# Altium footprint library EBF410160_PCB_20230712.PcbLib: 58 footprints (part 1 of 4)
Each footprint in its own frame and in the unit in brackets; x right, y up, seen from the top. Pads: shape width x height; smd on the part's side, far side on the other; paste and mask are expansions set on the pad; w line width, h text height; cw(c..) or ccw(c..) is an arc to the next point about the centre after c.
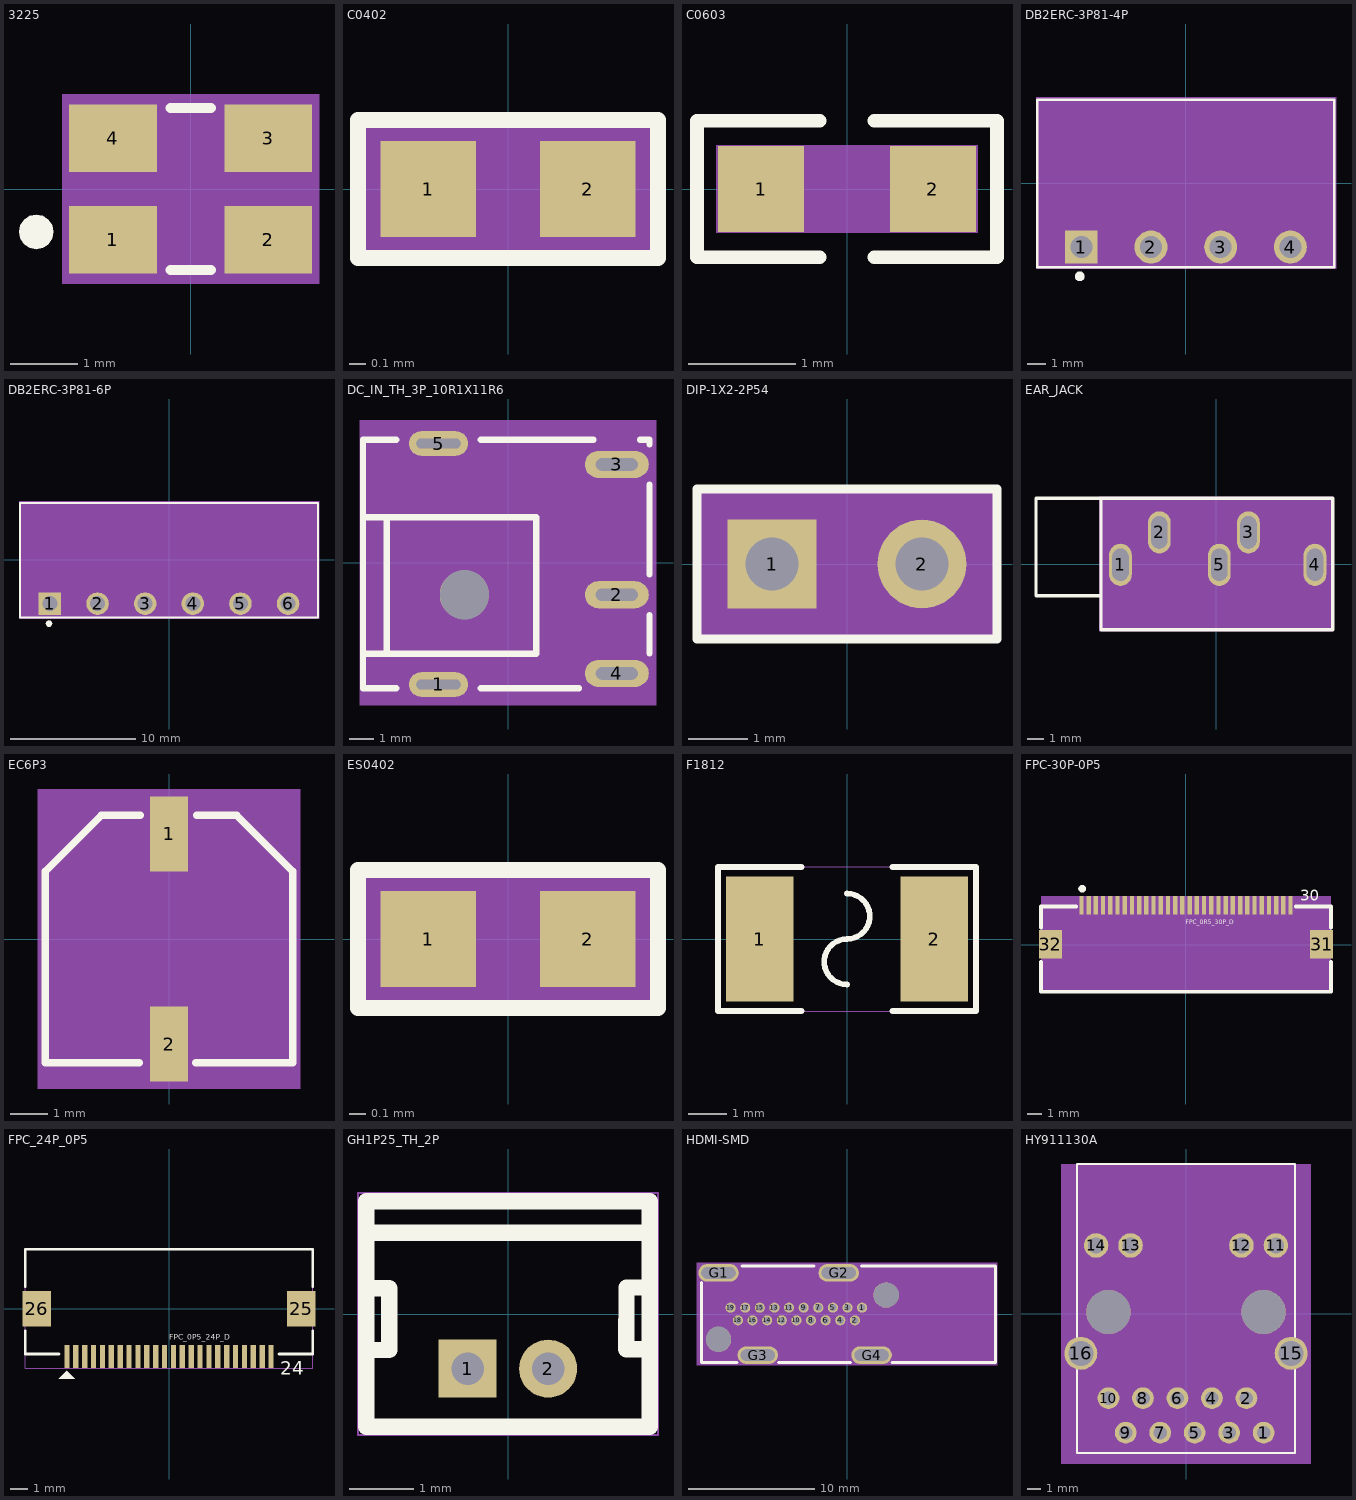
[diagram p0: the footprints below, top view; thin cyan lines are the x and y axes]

## 3225 [mm] "3225"
pads (4):
  rect 1.3x1 smd: 1(-1.15,-0.75) 2(1.15,-0.75) 3(1.15,0.75) 4(-1.15,0.75)
Top Overlay:
  dashed: -2.541,-0.635 -2.521,-0.733 -2.466,-0.815 -2.384,-0.87 -2.286,-0.89 -2.188,-0.87 -2.161,-0.852 -2.106,-0.815 -2.051,-0.733 -2.031,-0.635 -2.051,-0.537 -2.106,-0.455 -2.161,-0.418 -2.188,-0.4 -2.286,-0.38 -2.384,-0.4 -2.466,-0.455 -2.521,-0.537
  lines w0.15: -0.3,-1.2 0.3,-1.2 ; -0.3,1.2 0.3,1.2
Top 3D Body:
  region: -1.9,1.4 -1.9,-1.4 1.9,-1.4 1.9,1.4
Mechanical 20:
  text "3" at 1.516,0.75 h0.91
  text "1" at -0.784,-0.75 h0.91
  text "4" at -0.784,0.75 h0.91
  text "2" at 1.516,-0.75 h0.91
Top Assembly:
  lines w0.15: -1.6,-1.25 -1.6,1.25 1.6,1.25 1.6,-1.25 -1.6,-1.25
3D body: height 3.81, standoff 0, extent -1.9,-1.4 1.9,1.4

## C0402 [mm] "C0402"
pads (2):
  rect 0.599x0.599 smd: 1(-0.5,0) 2(0.5,0)
Top Overlay:
  lines w0.102: -0.94,-0.432 0.94,-0.432 0.94,0.432 -0.94,0.432 -0.94,-0.432
Top 3D Body:
  region: 0.94,0.432 0.94,-0.432 -0.94,-0.432 -0.94,0.432
Mechanical 20:
  text "1" at -0.5,0.254 h0.64
  text "2" at 0.5,0.254 h0.64
Top Assembly:
  dashed: -0.94,-0.432 -0.94,0.432 0.94,0.432 0.94,-0.432
3D body: height 3.81, standoff 0, extent -0.94,-0.432 0.94,0.432

## C0603 [mil] "C0603"
pads (2):
  rect 31.5x31.5 smd: 1(-31.5,0) 2(31.5,0)
Top Overlay:
  lines w5: -10,-25 -55,-25 -55,25 -10,25 ; 10,-25 55,-25 55,25 10,25
Top 3D Body:
  region: -48,16 48,16 48,-16 -48,-16
Mechanical 20:
  text "1" at -13.5,0 h45
  text "2" at 49.5,0 h45
Top Assembly:
  text "C0603" at -117,37 h45
3D body: height 150, standoff 0, extent -48,-16 48,16

## DB2ERC-3P81-4P [mm] "DB2ERC-3P81-4P"
pads (4):
  rect 1.8x1.8 / inner round 1.524 / far side rect 1.8x1.8 hole 1.2: 1(-5.725,-3.5)
  round 1.8 / inner round 1.524 / far side round 1.8 hole 1.2: 2(-1.915,-3.5) 3(1.895,-3.5) 4(5.705,-3.5)
Top Overlay:
  dashed: -6.065,-5.1 -6.045,-5.198 -5.99,-5.28 -5.908,-5.335 -5.81,-5.355 -5.712,-5.335 -5.685,-5.317 -5.63,-5.28 -5.574,-5.198 -5.555,-5.1 -5.574,-5.002 -5.63,-4.92 -5.685,-4.883 -5.712,-4.864 -5.81,-4.845 -5.908,-4.864 -5.99,-4.92 -6.045,-5.002
  lines w0.15: -8.13,-4.6 -8.13,4.55 8.11,4.55 8.11,-4.6 -8.13,-4.6
Top 3D Body:
  region: -8.2,4.7 -8.2,-4.7 8.2,-4.7 8.2,4.7
Mechanical 20:
  text "4" at 5.959,-3.5 h0.64
  text "3" at 2.149,-3.5 h0.64
  text "2" at -1.661,-3.5 h0.64
  text "1" at -5.471,-3.5 h0.64
3D body: height 3.81, standoff 0, extent -8.2,-4.7 8.2,4.7

## DB2ERC-3P81-6P [mm] "DB2ERC-3P81-6P"
pads (6):
  rect 1.8x1.8 / inner round 1.524 / far side rect 1.8x1.8 hole 1.2: 1(-9.525,-3.5)
  round 1.8 hole 1.2: 2(-5.715,-3.5) 5(5.715,-3.5)
  round 1.8 / inner round 1.524 / far side round 1.8 hole 1.2: 3(-1.905,-3.5) 4(1.905,-3.5) 6(9.525,-3.5)
Top Overlay:
  dashed: -9.855,-5.1 -9.836,-5.198 -9.78,-5.28 -9.698,-5.335 -9.6,-5.355 -9.502,-5.335 -9.475,-5.317 -9.42,-5.28 -9.364,-5.198 -9.345,-5.1 -9.364,-5.002 -9.42,-4.92 -9.475,-4.883 -9.502,-4.864 -9.6,-4.845 -9.698,-4.864 -9.78,-4.92 -9.836,-5.002
  lines w0.15: -11.93,-4.6 -11.93,4.55 11.93,4.55 11.93,-4.6 -11.93,-4.6
Top 3D Body:
  region: -12,4.7 -12,-4.7 12,-4.7 12,4.7
Mechanical 20:
  text "6" at 9.779,-3.5 h0.64
  text "4" at 2.159,-3.5 h0.64
  text "2" at -5.461,-3.5 h0.64
  text "5" at 5.969,-3.5 h0.64
  text "1" at -9.271,-3.5 h0.64
  text "3" at -1.651,-3.5 h0.64
3D body: height 3.81, standoff 0, extent -12,-4.7 12,4.7

## DC_IN_TH_3P_10R1X11R6 [mil] "DC_IN_TH_3P_10R1X11R6"
pads (6):
  oval 94.5x39.4 hole 70.9 slot 15.7 at 90 deg: 1(-111.25,-194.9) 5(-111.25,190.9)
  oval 102.4x43.3 hole 66.9 slot 19.7 at 90 deg: 2(174.25,-51.2) 3(174.25,157.4)
  oval 102.4x43.3 / inner round 60 / far side oval 102.4x43.3 hole 66.9 slot 19.7 at 90 deg: 4(174.25,-177.2)
  round 78.7 hole 78.7 unplated: ""(-69.85,-51.2)
Top Overlay:
  lines w10: -232.25,-145.7 45.25,-145.7 45.25,72.8 -222.45,72.8 -232.25,72.8 ; -193.95,-145.7 -193.95,72.8 ; -178.95,-200.8 -232.25,-200.8 -232.25,196.8 -178.95,196.8 ; -43.45,-200.8 113.65,-200.8 ; -43.45,196.8 136.95,196.8 ; 211.45,196.8 226.35,196.8 226.35,189.7 ; 226.35,-145 226.35,-83.5 ; 226.35,-19 226.35,125.2
Top 3D Body:
  region: -237.25,-228.4 237.25,-228.4 237.25,228.4 -237.25,228.4
Mechanical 20:
  text "4" at 174.25,-187.2 h25
  text "5" at -111.25,180.9 h25
  text "1" at -111.25,-204.9 h25
  text "2" at 174.25,-61.2 h25
  text "3" at 174.25,147.4 h25
Mechanical 23:
  dashed: -232.25,-141.8 41.35,-141.8 41.35,68.9 -232.25,68.9 -232.25,78.7 51.15,78.7 51.15,-151.6 -232.25,-151.6
3D body: height 150, standoff 0, extent -237.25,-228.4 237.25,228.4

## DIP-1X2-2P54 [mm] "DIP-1X2-2P54"
pads (2):
  rect 1.5x1.5 hole 0.9: 1(-1.27,0)
  round 1.5 / inner round 1.524 / far side round 1.5 hole 0.9: 2(1.27,0)
Top Overlay:
  lines w0.15: -2.54,-1.27 -2.54,1.27 2.54,1.27 2.54,-1.27 -2.54,-1.27
Bottom Overlay:
  lines w0.6: 0,-0.6 0,0.6
Top 3D Body:
  region: -2.54,-1.27 2.54,-1.27 2.54,1.27 -2.54,1.27
Mechanical 20:
  text "2" at 1.524,0 h0.64
  text "1" at -1.016,0 h0.64
Top Assembly:
  lines w0.025: -2.54,-1.27 -2.54,1.27 2.54,1.27 2.54,-1.27 -2.54,-1.27
3D body: height 3.81, standoff 0, extent -2.54,-1.27 2.54,1.27

## EAR_JACK [mm] "EAR_JACK"
pads (5):
  oval 1.4x2.6 / inner round 1.524 / far side oval 1.4x2.6 hole 1 slot 2 at 90 deg: 1(-5.904,-0.05) 2(-3.504,1.95) 3(1.996,1.95) 4(6.096,-0.05) 5(0.196,-0.05)
Top Overlay:
  lines w0.2: -7.18,-1.956 -11.117,-1.956 -11.117,4.064 -7.18,4.064 7.196,4.064 7.196,-4.064 -7.104,-4.064 -7.104,4.064
Top 3D Body:
  region: -7.2,-4.15 7.2,-4.15 7.2,4.15 -7.2,4.15
Mechanical 20:
  text "1" at -5.904,-0.304 h0.64
  text "5" at 0.196,-0.304 h0.64
  text "3" at 1.996,1.696 h0.64
  text "2" at -3.504,1.696 h0.64
  text "4" at 6.096,-0.304 h0.64
Top Assembly:
  dashed: -7.2,4.15 -7.2,-4.15 7.2,-4.15 7.2,4.15
3D body: height 3.81, standoff 0, extent -7.2,-4.15 7.2,4.15

## EC6P3 [mm] "EC6P3"
pads (2):
  rect 1.001x1.999 smd: 1(0,2.8) 2(0,-2.8)
Top Overlay:
  lines w0.2: -0.787,-3.3 -3.3,-3.3 -3.3,1.8 -1.8,3.3 -0.762,3.3 ; 0.711,-3.3 3.3,-3.3 3.3,1.8 1.8,3.3 0.737,3.3
Top 3D Body:
  region: -3.5,4 -3.5,-4 3.5,-4 3.5,4
Mechanical 20:
  text "1" at 0.356,2.8 h0.89
  text "2" at 0.356,-2.8 h0.89
3D body: height 3.81, standoff 0, extent -3.5,-4 3.5,4

## ES0402 [mm] "ES0402"
pads (2):
  rect 0.599x0.599 smd: 1(-0.5,0) 2(0.5,0)
Top Overlay:
  lines w0.102: -0.94,-0.432 -0.94,0.432 0.94,0.432 0.94,-0.432 -0.94,-0.432
Top 3D Body:
  region: 0.94,0.432 0.94,-0.432 -0.94,-0.432 -0.94,0.432
Mechanical 20:
  text "1" at -0.5,-0.254 h0.64
  text "2" at 0.5,-0.254 h0.64
Top Assembly:
  dashed: -0.94,-0.432 -0.94,0.432 0.94,0.432 0.94,-0.432
3D body: height 3.81, standoff 0, extent -0.94,-0.432 0.94,0.432

## F1812 [mm] "F1812"
pads (2):
  rect 1.78x3.3 smd: 1(-2.305,0) 2(2.305,0)
Top Overlay:
  lines w0.15: -1.2,-1.9 -3.4,-1.9 -3.4,1.9 -1.2,1.9 ; 0,-1.2 cw(c0,-0.6) 0,0 ccw(c0,0.6) 0,1.2 ; 1.2,-1.9 3.4,-1.9 3.4,1.9 1.2,1.9
Top 3D Body:
  lines w0.025: -3.4,-1.9 -3.4,1.9 3.4,1.9 3.4,-1.9 -3.4,-1.9
Mechanical 20:
  text "1" at -2.425,0 h0.3
  text "2" at 2.185,0 h0.3

## FPC-30P-0P5 [mm] "FPC-30P-0P5"
pads (32):
  rect 0.3x1.3 smd: 1(-7.25,2.733) 2(-6.75,2.733) 3(-6.25,2.733) 4(-5.75,2.733) 5(-5.25,2.733) 6(-4.75,2.733) 7(-4.25,2.733) 8(-3.75,2.733) 9(-3.25,2.733) 10(-2.75,2.733) 11(-2.25,2.733) 12(-1.75,2.733) 13(-1.25,2.733) 14(-0.75,2.733) 15(-0.25,2.733) 16(0.25,2.733) 17(0.75,2.733) 18(1.25,2.733) 19(1.75,2.733) 20(2.25,2.733) 21(2.75,2.733) 22(3.25,2.733) 23(3.75,2.733) 24(4.25,2.733) 25(4.75,2.733) 26(5.25,2.733) 27(5.75,2.733) 28(6.25,2.733) 29(6.75,2.733) 30(7.25,2.733)
  rect 1.6x2 smd: 31(9.4,0.032) 32(-9.4,0.032)
Top Overlay:
  dashed: -7.2,3.628 -7.102,3.647 -7.02,3.702 -6.964,3.785 -6.945,3.882 -6.964,3.98 -6.983,4.008 -7.02,4.063 -7.102,4.118 -7.2,4.137 -7.297,4.118 -7.38,4.063 -7.417,4.008 -7.435,3.98 -7.455,3.882 -7.435,3.785 -7.38,3.702 -7.297,3.647
  lines w0.254: -10.05,-1.199 -10.05,-3.257 ; -10.05,1.164 -10.05,2.652 -7.631,2.652 ; 7.631,2.652 10.05,2.652 10.05,1.164 ; 10.05,-1.199 10.05,-3.268 -10.04,-3.268 -10.05,-3.257 ; -10.05,-3.257 -10.05,-3.257
  text "FPC_0R5_30P_D" at 0,1.433 h0.3
  text "30" at 7.925,3.049 h0.76
Top 3D Body:
  region: 10.052,-3.35 10.052,3.35 -10.052,3.35 -10.052,-3.35
Mechanical 20:
  text "3" at -6.25,2.813 h0.1
  text "2" at -6.75,2.813 h0.1
  text "1" at -7.25,2.813 h0.1
  text "5" at -5.25,2.813 h0.1
  text "4" at -5.75,2.813 h0.1
  text "14" at -0.75,2.893 h0.1
  text "12" at -1.75,2.893 h0.1
  text "11" at -2.25,2.893 h0.1
  text "13" at -1.25,2.893 h0.1
  text "28" at 6.25,2.893 h0.1
  text "25" at 4.75,2.893 h0.1
  text "22" at 3.25,2.893 h0.1
  text "19" at 1.75,2.893 h0.1
  text "16" at 0.25,2.893 h0.1
  text "8" at -3.75,2.813 h0.1
  text "7" at -4.25,2.813 h0.1
  text "6" at -4.75,2.813 h0.1
  text "31" at 8.89,0.112 h0.1
  text "32" at -10.16,0.112 h0.1
  text "30" at 7.25,2.893 h0.1
  text "29" at 6.75,2.893 h0.1
  text "27" at 5.75,2.893 h0.1
  text "26" at 5.25,2.893 h0.1
  text "24" at 4.25,2.893 h0.1
  text "23" at 3.75,2.893 h0.1
  text "21" at 2.75,2.893 h0.1
  text "20" at 2.25,2.893 h0.1
  text "18" at 1.25,2.893 h0.1
  text "17" at 0.75,2.893 h0.1
  text "15" at -0.25,2.893 h0.1
  text "9" at -3.25,2.813 h0.1
  text "10" at -2.75,2.893 h0.1
3D body: height 3.81, standoff 0, extent -10.052,-3.35 10.052,3.35

## FPC_24P_0P5 [mm] "FPC_24P_0P5"
pads (26):
  rect 0.3x1.3 smd: 1(-5.75,-2.701) 2(-5.25,-2.701) 3(-4.75,-2.701) 4(-4.25,-2.701) 5(-3.75,-2.701) 6(-3.25,-2.701) 7(-2.75,-2.701) 8(-2.25,-2.701) 9(-1.75,-2.701) 10(-1.25,-2.701) 11(-0.75,-2.701) 12(-0.25,-2.701) 13(0.25,-2.701) 14(0.75,-2.701) 15(1.25,-2.701) 16(1.75,-2.701) 17(2.25,-2.701) 18(2.75,-2.701) 19(3.25,-2.701) 20(3.75,-2.701) 21(4.25,-2.701) 22(4.75,-2.701) 23(5.25,-2.701) 24(5.75,-2.701)
  rect 1.6x2 smd: 25(7.45,0.001) 26(-7.45,0.001)
Top Overlay:
  dashed: -6.199,-3.95 -5.301,-3.95 -5.75,-3.501
  lines w0.15: -8.1,-1.25 -8.1,-2.55 -6.2,-2.55 ; -8.1,1.25 -8.1,3.35 8.1,3.35 8.1,1.25 ; 6.2,-2.55 8.1,-2.55 8.1,-1.25
  text "24" at 6.274,-3.729 h0.76
  text "FPC_0P5_24P_D" at 0,-1.737 h0.3
Top 3D Body:
  lines w0.025: -8.1,-3.35 8.1,-3.35 8.1,3.35 -8.1,3.35 -8.1,-3.35
Mechanical 20:
  text "5" at -3.75,-2.955 h0.64
  text "6" at -3.25,-2.955 h0.64
  text "9" at -1.75,-2.955 h0.64
  text "10" at -1.25,-3.209 h0.64
  text "26" at -7.45,-0.507 h0.64
  text "25" at 7.45,-0.507 h0.64
  text "24" at 5.75,-3.209 h0.64
  text "23" at 5.25,-3.209 h0.64
  text "4" at -4.25,-2.955 h0.64
  text "15" at 1.25,-3.209 h0.64
  text "22" at 4.75,-3.209 h0.64
  text "11" at -0.75,-3.209 h0.64
  text "12" at -0.25,-3.209 h0.64
  text "8" at -2.25,-2.955 h0.64
  text "7" at -2.75,-2.955 h0.64
  text "3" at -4.75,-2.955 h0.64
  text "2" at -5.25,-2.955 h0.64
  text "1" at -5.75,-2.955 h0.64
  text "21" at 4.25,-3.209 h0.64
  text "20" at 3.75,-3.209 h0.64
  text "19" at 3.25,-3.209 h0.64
  text "18" at 2.75,-3.209 h0.64
  text "17" at 2.25,-3.209 h0.64
  text "16" at 1.75,-3.209 h0.64
  text "14" at 0.75,-3.209 h0.64
  text "13" at 0.25,-3.209 h0.64

## GH1P25_TH_2P [mm] "GH1P25_TH_2P"
pads (2):
  rect 0.9x0.9 / inner round 1.524 / far side rect 0.9x0.9 hole 0.5: 1(-0.626,-0.849)
  round 0.9 hole 0.5: 2(0.624,-0.849)
Top Overlay:
  lines w0.254: -2.202,0.401 -1.841,0.401 -1.841,-0.559 -2.161,-0.559 ; -2.201,1.262 2.199,1.262 ; 2.159,-0.549 1.839,-0.548 1.839,0.411 2.2,0.411 ; 2.199,-1.749 -2.201,-1.749 -2.201,1.751 2.199,1.751 ; 2.202,-1.751 2.202,1.749
Bottom Overlay:
  lines w0.2: -0.001,-1.549 -0.001,-0.149
  lines w0.3: -1.401,-1.549 -1.401,-0.149 1.399,-0.149 1.399,-1.549 -1.101,-1.549 -1.401,-1.549
Top 3D Body:
  lines w0.025: -2.329,-1.878 2.329,-1.878 2.329,1.878 -2.329,1.878 -2.329,-1.878
Mechanical 20:
  text "1" at -0.88,-0.849 h0.64
  text "2" at 0.37,-0.849 h0.64

## HDMI-SMD [mm] "HDMI-SMD"
pads (25):
  round 0.8 / inner round 1.524 / far side round 0.8 hole 0.55: 1(1.194,0.5) 3(0.039,0.5) 4(-0.531,-0.5) 6(-1.687,-0.5) 7(-2.271,0.5) 9(-3.425,0.5) 10(-3.998,-0.5) 12(-5.154,-0.5) 13(-5.736,0.5) 14(-6.31,-0.5) 15(-6.891,0.5) 16(-7.467,-0.5) 18(-8.623,-0.5) 19(-9.2,0.5)
  round 0.8 hole 0.55: 2(0.626,-0.5) 5(-1.116,0.5) 8(-2.843,-0.5) 11(-4.581,0.5) 17(-8.045,0.5)
  oval 3.2x1.4 / inner round 1.524 / far side oval 3.2x1.4 hole 2.7 slot 0.9 at 90 deg: G1(-10.156,3.25) G2(-0.656,3.25) G3(-7.056,-3.25) G4(1.945,-3.25)
  round 2 hole 2 unplated: ""(-10.156,-2) ""(3.094,1.5)
Top Overlay:
  lines w0.254: -11.511,2.466 -11.511,-3.833 -8.699,-3.833 -8.696,-3.83 ; -8.295,3.786 -2.617,3.786 ; -5.422,-3.834 0.277,-3.834 ; 1.151,3.786 11.73,3.786 11.73,-3.834 3.588,-3.834 3.584,-3.83
Bottom Overlay:
  drawing of 20 lines, arcs and shapes, not listed
Top 3D Body:
  region: -11.857,-4.052 11.857,-4.052 11.857,4.052 -11.857,4.052
Mechanical 20:
  text "19" at -9.2,1.008 h0.64
  text "1" at 1.194,0.754 h0.64
  text "3" at 0.039,0.754 h0.64
  text "4" at -0.531,-0.246 h0.64
  text "6" at -1.687,-0.246 h0.64
  text "7" at -2.271,0.754 h0.64
  text "9" at -3.425,0.754 h0.64
  text "10" at -3.998,0.008 h0.64
  text "12" at -5.154,0.008 h0.64
  text "13" at -5.736,1.008 h0.64
  text "15" at -6.891,1.008 h0.64
  text "16" at -7.467,0.008 h0.64
  text "G1" at -10.156,3.758 h0.64
  text "G2" at -0.656,3.758 h0.64
  text "G3" at -7.056,-2.742 h0.64
  text "G4" at 1.945,-2.742 h0.64
  text "11" at -4.581,1.008 h0.64
  text "17" at -8.045,1.008 h0.64
  text "2" at 0.626,-0.246 h0.64
  text "5" at -1.116,0.754 h0.64
  text "8" at -2.843,-0.246 h0.64
  text "18" at -8.623,0.008 h0.64
  text "14" at -6.31,0.008 h0.64
3D body: height 3.81, standoff 0, extent -11.857,-4.052 11.857,4.052

## HY911130A [mm] "HY911130A"
pads (18):
  round 1.6 / inner round 1.524 / far side round 1.6 hole 1: 1(5.72,-8.74) 2(4.45,-6.2) 3(3.18,-8.74) 4(1.91,-6.2) 5(0.64,-8.74) 6(-0.63,-6.2) 7(-1.9,-8.74) 8(-3.17,-6.2) 9(-4.44,-8.74) 10(-5.71,-6.2)
  round 1.8 / inner round 1.524 / far side round 1.8 hole 1.2: 11(6.625,5.05) 12(4.085,5.05) 13(-4.085,5.05) 14(-6.625,5.05)
  round 2.43 hole 1.83: 15(7.745,-2.9) 16(-7.745,-2.9)
  round 3.25 hole 3.25 unplated: ""(-5.715,0.15) ""(5.715,0.15)
Top Overlay:
  lines w0.15: -8.02,-10.25 8.02,-10.25 8.02,11.05 -8.02,11.05 -8.02,-10.25
Bottom Overlay:
  drawing of 17 lines, arcs and shapes, not listed
Top 3D Body:
  region: -9.2,11.05 -9.2,-11.05 9.2,-11.05 9.2,11.05
Mechanical 20:
  text "2" at 4.044,-6.2 h1.02
  text "3" at 2.774,-8.74 h1.02
  text "4" at 1.504,-6.2 h1.02
  text "7" at -2.306,-8.74 h1.02
  text "5" at 0.234,-8.74 h1.02
  text "6" at -1.036,-6.2 h1.02
  text "8" at -3.576,-6.2 h1.02
  text "9" at -4.846,-8.74 h1.02
  text "13" at -4.898,5.05 h1.02
  text "10" at -6.523,-6.2 h1.02
  text "15" at 6.932,-2.9 h1.02
  text "16" at -8.558,-2.9 h1.02
  text "1" at 5.314,-8.74 h1.02
  text "14" at -7.438,5.05 h1.02
  text "11" at 5.812,5.05 h1.02
  text "12" at 3.272,5.05 h1.02
3D body: height 3.81, standoff 0, extent -9.2,-11.05 9.2,11.05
